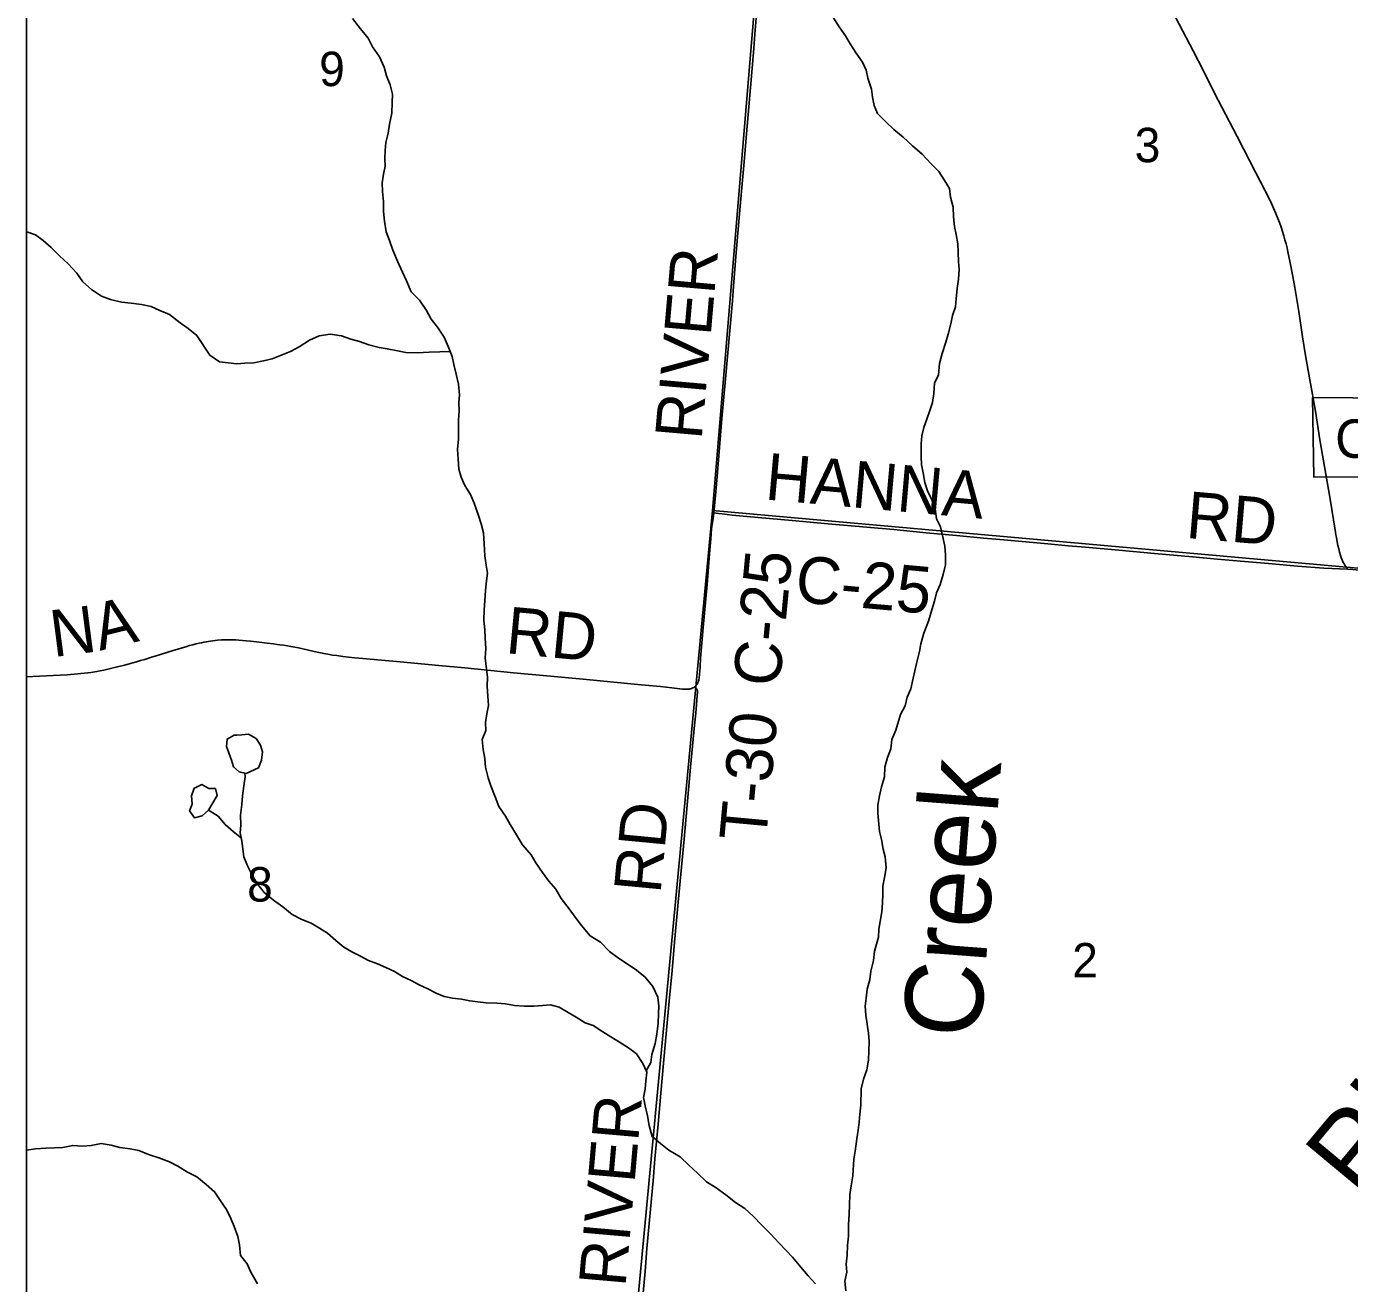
# Model space of a CAD drawing. Extents: x 0 to 1067, y 0 to 440.
# Drawn here: x 131 to 227.4, y 260 to 351.6 of the extents above; entities that cross this region are included whole.
import ezdxf

# ---------------------------------------------------------------- set-up
doc = ezdxf.new("R2010")
doc.units = 0
for name, color, linetype in [('GM_X_County_Road', 7, 'Continuous'), ('GM_X_County_Road_Text', 7, 'Continuous'), ('GM_X_Major_River_Text', 7, 'Continuous'), ('GM_X_Minor_Lake', 7, 'Continuous'), ('GM_X_Minor_River', 7, 'Continuous'), ('GM_X_Minor_River_Text', 7, 'Continuous'), ('GM_X_Section', 7, 'Continuous'), ('GM_X_Section_Text', 7, 'Continuous'), ('GM_X_State_Route', 7, 'Continuous'), ('GM_X_Township_Road', 7, 'Continuous'), ('GM_X_Township_Road_Text', 7, 'Continuous'), ('SH_Text', 7, 'Continuous')]:
    doc.layers.add(name, color=color, linetype=linetype)

msp = doc.modelspace()

# ---------------------------------------------------------------- linework, layer by layer
at = {"layer": 'GM_X_County_Road'}
for points in [[(179.683, 303.484), (179.722, 303.512), (179.774, 303.562), (179.809, 303.603), (179.837, 303.641), (179.898, 303.731), (179.93, 303.798), (179.955, 303.85), (179.971, 303.902), (179.986, 303.959), (179.996, 304.008), (180.014, 304.109), (180.03, 304.215), (180.043, 304.316), (180.053, 304.447), (180.064, 304.597), (180.084, 304.933), (180.123, 305.569), (180.172, 306.137), (180.315, 307.813), (180.606, 310.945), (180.769, 313.184), (180.865, 314.264), (180.929, 315.009), (180.95, 315.162), (180.97, 315.322), (180.993, 315.478), (181.034, 315.764), (181.059, 315.944), (181.089, 316.159)], [(181.089, 316.159), (181.248, 316.14), (181.433, 316.117), (181.694, 316.085), (182.429, 316.001), (183.494, 315.897), (186.789, 315.601), (188.619, 315.434), (189.96, 315.315), (191.671, 315.162), (192.495, 315.088), (194.197, 314.94), (196.554, 314.717), (198.781, 314.507), (200.746, 314.329), (202.216, 314.195), (203.565, 314.071), (205.421, 313.906), (206.902, 313.771), (208.168, 313.651), (210.606, 313.436), (213.2, 313.204), (215.977, 312.948), (217.792, 312.785), (219.453, 312.638), (221.511, 312.464), (223.627, 312.287), (225.535, 312.144), (227.25, 312.068)], [(131, 304.202), (131.941, 304.255), (133.46, 304.329), (133.963, 304.359), (134.22, 304.378), (134.491, 304.397), (134.732, 304.417), (134.964, 304.442), (135.235, 304.471), (135.462, 304.501), (135.689, 304.536), (136.123, 304.61), (136.38, 304.659), (136.635, 304.707), (136.937, 304.773), (137.218, 304.837), (137.514, 304.906), (137.845, 304.99), (138.155, 305.069), (138.413, 305.133), (138.747, 305.226), (139.028, 305.305), (139.319, 305.389), (139.633, 305.482), (140.044, 305.611), (140.459, 305.734), (140.849, 305.853), (141.702, 306.129), (142.032, 306.227), (142.348, 306.321), (142.614, 306.4), (142.885, 306.484), (143.127, 306.548), (143.378, 306.612), (143.595, 306.662), (143.754, 306.696), (143.931, 306.731), (144.118, 306.77), (144.261, 306.795), (144.414, 306.82), (144.587, 306.844), (144.74, 306.864), (144.932, 306.884), (145.223, 306.903), (145.43, 306.913), (145.628, 306.918), (145.845, 306.918), (146.032, 306.913), (146.264, 306.899), (146.476, 306.884), (146.747, 306.864), (147.009, 306.844), (147.319, 306.815), (147.753, 306.77), (148.163, 306.721), (148.533, 306.676), (148.996, 306.617), (149.262, 306.578), (149.474, 306.548), (149.736, 306.509), (150.017, 306.464), (150.273, 306.42), (150.56, 306.366), (150.816, 306.312), (152.173, 306.016), (152.424, 305.961), (152.666, 305.912), (152.968, 305.857), (153.307, 305.798), (153.618, 305.754), (154.042, 305.695), (154.456, 305.645), (154.934, 305.596), (155.521, 305.537), (158.23, 305.294), (161.06, 305.029), (162.937, 304.862), (166.495, 304.511), (168.922, 304.284), (171.566, 304.038), (175.802, 303.629), (177.208, 303.498), (178.022, 303.414), (178.801, 303.322), (178.979, 303.308), (179.098, 303.305), (179.195, 303.305), (179.278, 303.315), (179.342, 303.325), (179.412, 303.344), (179.472, 303.364), (179.52, 303.384), (179.569, 303.409), (179.623, 303.443), (179.683, 303.484)]]:
    msp.add_lwpolyline(points, dxfattribs=at)
at = {"layer": 'GM_X_Minor_Lake'}
for points in [[(146.341, 299.969), (146.123, 299.955), (145.619, 299.667), (145.565, 299.123), (145.74, 298.665), (145.936, 298.139), (146.087, 297.66), (146.49, 297.29), (147.01, 297.168)], [(147.01, 297.168), (147.901, 297.585), (148.136, 298.127), (148.191, 298.74), (148.063, 299.22), (147.73, 299.725), (147.19, 300.029), (146.691, 299.991), (146.341, 299.969)], [(143.348, 296.149), (143.227, 296.091), (143.014, 295.526), (143.073, 294.934), (142.884, 294.437), (143.239, 293.931), (143.808, 294.081), (144.268, 294.483)], [(144.268, 294.483), (144.898, 295.564), (144.769, 296.066), (144.293, 296.074), (143.775, 296.355), (143.348, 296.149)]]:
    msp.add_lwpolyline(points, dxfattribs=at)
at = {"layer": 'GM_X_Minor_River'}
for points in [[(157.147, 342.574), (157.188, 343.166), (157.367, 343.844), (157.454, 344.503), (157.614, 345.296), (157.637, 346.07), (157.678, 346.685), (157.493, 347.374), (157.239, 348.02), (157.076, 348.664), (156.733, 349.404), (156.208, 350.127), (155.908, 350.774), (155.336, 351.452), (154.766, 352.199)], [(198.255, 339.82), (197.864, 340.448), (197.472, 341.052), (196.897, 341.64), (196.257, 342.32), (195.568, 342.911), (194.881, 343.548), (194.215, 344.115), (193.617, 344.68), (193.019, 345.268), (192.763, 345.869), (192.644, 346.465), (192.571, 347.06), (192.321, 347.866), (192.179, 348.44), (191.922, 349.018), (191.464, 349.67), (191.029, 350.367), (190.681, 350.947), (190.222, 351.599), (189.765, 352.32)], [(176.153, 275.489), (176.49, 276.09), (176.576, 276.681), (176.804, 277.474), (176.938, 278.155), (177.029, 278.951), (177.049, 279.636), (177.089, 280.205), (177.016, 280.847), (176.652, 281.635), (176.08, 282.314), (175.457, 282.813), (174.765, 283.291), (174.14, 283.698), (173.493, 284.175), (172.83, 284.857), (172.07, 285.337), (171.455, 286.087), (170.972, 286.696), (170.534, 287.303), (169.964, 288.051), (169.574, 288.725), (169.067, 289.311), (168.607, 289.942), (168.127, 290.642), (167.78, 291.223), (167.141, 291.973), (166.707, 292.695), (166.251, 293.439), (165.904, 294.043), (165.424, 294.766), (165.148, 295.459), (164.831, 296.268), (164.643, 296.845), (164.438, 297.627), (164.41, 298.245), (164.27, 298.911), (164.201, 299.643), (164.47, 300.297), (164.442, 300.869), (164.551, 301.505), (164.66, 302.118), (164.612, 302.804), (164.565, 303.536), (164.607, 304.197), (164.51, 304.77), (164.42, 305.595), (164.463, 306.278), (164.417, 307.033), (164.411, 307.627), (164.318, 308.337), (164.34, 309.09), (164.405, 309.75), (164.45, 310.502), (164.516, 311.207), (164.601, 311.775), (164.504, 312.349), (164.41, 313.036), (164.345, 313.906), (164.3, 314.706), (164.137, 315.372), (163.95, 315.972), (163.612, 316.872), (163.357, 317.496), (162.944, 318.17), (162.688, 318.772), (162.5, 319.348), (162.454, 320.102), (162.406, 320.788), (162.474, 321.562), (162.492, 322.155), (162.492, 322.931), (162.534, 323.614), (162.506, 324.208), (162.546, 324.777), (162.477, 325.555), (162.316, 326.267), (162.132, 326.98), (162.012, 327.554), (161.738, 328.292), (161.439, 328.963), (160.96, 329.708), (160.499, 330.292), (160.153, 330.919), (159.651, 331.664), (159.031, 332.276), (158.691, 333.085), (158.413, 333.71), (158.027, 334.52), (157.708, 335.305), (157.456, 336.02), (157.201, 336.643), (157.087, 337.422), (157.017, 338.131), (157.016, 338.861), (156.946, 339.593), (156.919, 340.232), (157.028, 340.845), (157.137, 341.434), (157.108, 342.005), (157.147, 342.574)], [(191.397, 269.628), (191.514, 270.538), (191.6, 271.152), (191.686, 271.743), (191.726, 272.335), (191.79, 272.973), (191.826, 274.182), (192.005, 274.885), (192.23, 275.563), (192.365, 276.267), (192.405, 277.636), (192.354, 278.232), (192.259, 278.897), (192.164, 279.539), (192.115, 280.203), (192.178, 280.772), (192.265, 281.432), (192.445, 282.134), (192.531, 282.748), (192.713, 283.519), (192.801, 284.202), (193.082, 285.221), (193.122, 285.813), (193.207, 286.382), (193.318, 287.086), (193.383, 287.724), (193.402, 288.385), (193.396, 288.956), (193.528, 289.592), (193.639, 290.273), (193.572, 291.075), (193.429, 291.65), (193.313, 292.361), (193.171, 292.936), (193.027, 294.265), (193.045, 294.858), (193.156, 295.54), (193.312, 296.197), (193.515, 296.922), (193.536, 297.629), (193.738, 298.331), (193.984, 298.962), (194.05, 299.645), (194.343, 300.321), (194.695, 301.475), (195.033, 302.104), (195.164, 302.717), (195.433, 303.325), (195.615, 304.118), (195.851, 305.184), (196.081, 306.045), (196.166, 306.613), (196.394, 307.405), (196.738, 308.262), (196.968, 309.1), (197.168, 309.733), (197.322, 310.322), (197.591, 310.953), (197.794, 311.677), (197.974, 312.379), (197.973, 313.11), (197.923, 313.727), (197.741, 314.509), (197.6, 315.152), (197.321, 315.731), (197.206, 316.465), (196.953, 317.157), (196.652, 317.76), (196.465, 318.382), (196.349, 319.07), (196.23, 319.667), (196.202, 320.261), (196.184, 321.197), (196.246, 321.789), (196.378, 322.378), (196.6, 322.988), (196.824, 323.62), (197.023, 324.207), (197.111, 324.866), (197.178, 325.617), (197.447, 326.225), (197.539, 327.044), (197.72, 327.791), (197.994, 328.604), (198.171, 329.192), (198.352, 329.94), (198.484, 330.552), (198.685, 331.185), (198.748, 331.776), (198.815, 332.527), (198.926, 333.208), (198.97, 333.914), (198.918, 334.486), (198.892, 335.148), (198.865, 335.787), (198.748, 336.452), (198.629, 337.049), (198.558, 337.735), (198.533, 338.443), (198.327, 339.179), (198.255, 339.82)], [(161.872, 327.931), (161.112, 327.901), (160.337, 327.879), (159.47, 327.837), (158.651, 327.862), (158.04, 327.972), (157.293, 328.132), (156.704, 328.219), (155.958, 328.424), (155.259, 328.651), (154.627, 328.83), (153.951, 329.079), (153.135, 329.195), (152.334, 329.06), (151.619, 328.763), (150.876, 328.261), (150.229, 327.938), (148.892, 327.386), (148.273, 327.246), (147.563, 327.108), (146.902, 327.082), (146.332, 327.031), (145.696, 327.097), (145.061, 327.185), (144.369, 327.662), (143.409, 329.106), (142.787, 329.604), (142.206, 330.01), (141.428, 330.627), (140.708, 330.923), (140.079, 331.216), (139.377, 331.352), (138.628, 331.443), (137.925, 331.533), (137.133, 331.717), (136.48, 331.965), (135.743, 332.444), (135.099, 333.011), (134.662, 333.641), (134.044, 334.321), (133.402, 334.911), (132.804, 335.5), (132.227, 336.019), (131.647, 336.425), (131.016, 336.649), (131, 336.652)], [(188.496, 259.963), (187.967, 260.55), (187.415, 261.161), (186.822, 261.91), (185.85, 262.922), (185.21, 263.604), (184.591, 264.24), (183.95, 264.899), (183.351, 265.442), (182.659, 265.898), (181.969, 266.444), (181.255, 266.968), (180.562, 267.401), (179.897, 268.015), (179.277, 268.605), (178.635, 269.218), (177.806, 269.701), (177.206, 270.199), (176.583, 270.697), (176.379, 271.503), (176.263, 272.215), (176.079, 272.928), (175.961, 273.548), (176.092, 274.138), (176.132, 274.754), (176.197, 275.391), (175.919, 276.016), (175.461, 276.716), (174.86, 277.168), (174.211, 277.576), (173.585, 277.961), (173.004, 278.321), (172.289, 278.8), (171.702, 278.978), (171.054, 279.408), (170.472, 279.746), (169.823, 280.131), (169.19, 280.288), (168.598, 280.26), (167.981, 280.188), (167.276, 280.21), (166.571, 280.254), (165.914, 280.366), (165.278, 280.408), (164.504, 280.432), (163.892, 280.519), (163.302, 280.583), (162.691, 280.716), (162.033, 280.781), (161.445, 280.914), (160.86, 281.16), (160.254, 281.475), (159.625, 281.746), (159.042, 282.061), (158.413, 282.354), (157.809, 282.738), (157.18, 283.008), (156.573, 283.278), (155.92, 283.527), (155.337, 283.841), (154.709, 284.157), (154.127, 284.495), (153.549, 284.992), (152.927, 285.514), (152.346, 285.897), (151.742, 286.258), (151.066, 286.507), (150.372, 286.894), (149.682, 287.44), (148.99, 287.918), (148.323, 288.486), (147.797, 289.165), (147.428, 289.792), (147.105, 290.442), (146.851, 291.089), (146.703, 292.235), (146.561, 292.833), (146.623, 293.402), (146.599, 294.133), (146.69, 294.907), (146.754, 295.544), (146.843, 296.272), (146.93, 296.909), (146.908, 297.205)], [(146.667, 292.443), (146.064, 292.933), (145.485, 293.446), (144.975, 294.047), (144.393, 294.423), (144.268, 294.483)], [(147.832, 259.954), (147.356, 260.814), (147.077, 261.416), (146.594, 262.025), (146.526, 262.803), (146.407, 263.401), (146.132, 264.14), (145.899, 264.718), (145.576, 265.368), (145.096, 266.09), (144.703, 266.673), (144.104, 267.194), (143.415, 267.763), (142.742, 268.104), (142.026, 268.537), (141.42, 268.852), (140.655, 269.15), (139.887, 269.378), (139.19, 269.674), (138.556, 269.807), (137.808, 269.899), (137.175, 270.055), (136.45, 270.191), (135.717, 270.031), (135.101, 270.004), (134.374, 270.049), (133.64, 269.889), (133.048, 269.884), (132.41, 269.858), (131.657, 269.789), (131, 269.703)], [(190.712, 259.438), (190.641, 260.149), (190.774, 260.807), (190.723, 261.38), (190.81, 262.039), (190.832, 262.77), (190.897, 263.43), (190.898, 264.252), (190.944, 265.05), (190.985, 265.689), (191.008, 266.465), (191.095, 267.101), (191.207, 267.829), (191.288, 269.037), (191.397, 269.628)]]:
    msp.add_lwpolyline(points, dxfattribs=at)
at = {"layer": 'GM_X_Section'}
for points in [[(185.99, 376.405), (246.65, 370.913), (240.782, 310.986), (180.984, 316.33)], [(180.984, 316.33), (240.782, 310.986), (235.406, 252.097), (175.453, 257.739)]]:
    msp.add_lwpolyline(points, close=True, dxfattribs=at)
at = {"layer": 'GM_X_State_Route'}
for points in [[(214.756, 352.26), (216.008, 349.845), (216.76, 348.386), (217.557, 346.817), (219.225, 343.597), (220.576, 340.948), (221.548, 339.079), (221.72, 338.714), (221.873, 338.383), (222.036, 337.999), (222.189, 337.629), (222.307, 337.328), (222.425, 336.998), (222.529, 336.677), (222.622, 336.357), (222.706, 336.06), (222.781, 335.78), (222.854, 335.483), (222.921, 335.198), (223.086, 334.393), (223.279, 333.387), (223.422, 332.598), (223.708, 330.847), (223.984, 328.998), (224.191, 327.646), (224.522, 325.863), (224.921, 323.567), (225.257, 321.476), (225.609, 319.393), (225.967, 317.298), (226.393, 314.762), (226.42, 314.561), (226.454, 314.358), (226.514, 314.043), (226.564, 313.789), (226.618, 313.54), (226.677, 313.308), (226.751, 313.052), (226.802, 312.902), (226.843, 312.791), (226.898, 312.662), (226.95, 312.555), (227.007, 312.449), (227.074, 312.354), (227.14, 312.246), (227.201, 312.148), (227.25, 312.068)], [(227.25, 312.068), (227.659, 312.025), (228.597, 311.945), (232.88, 311.581), (238.674, 311.072), (241.117, 310.852)]]:
    msp.add_lwpolyline(points, dxfattribs=at)
at = {"layer": 'GM_X_Township_Road'}
for points in [[(252.4, 425.107), (131, 425.107), (131, 200.68)], [(184.245, 353.115), (184.082, 351.072), (183.992, 350.032), (183.927, 349.14), (183.465, 343.793), (183.3, 341.749), (183.181, 340.413), (183.016, 338.519), (182.722, 335.14), (182.531, 332.687), (182.438, 331.61), (181.915, 325.669), (181.681, 323.033), (181.346, 319.097), (181.203, 317.425), (181.089, 316.159)], [(181.089, 316.159), (181.059, 315.944), (181.034, 315.764), (180.993, 315.478), (180.97, 315.322), (180.95, 315.162), (180.929, 315.009), (180.865, 314.264), (180.769, 313.184), (180.606, 310.945), (180.315, 307.813), (180.172, 306.137), (180.123, 305.569), (180.084, 304.933), (180.064, 304.597), (180.053, 304.447), (180.043, 304.316), (180.03, 304.215), (180.014, 304.109), (179.996, 304.008), (179.986, 303.959), (179.971, 303.902), (179.955, 303.85), (179.93, 303.798), (179.898, 303.731), (179.837, 303.641), (179.809, 303.603), (179.774, 303.562), (179.722, 303.512), (179.683, 303.484)], [(179.683, 303.484), (179.768, 303.391), (179.825, 303.33), (179.869, 303.27), (179.896, 303.209), (179.899, 303.14), (179.768, 301.571), (179.685, 300.681), (179.397, 297.623), (179.119, 294.594), (178.914, 292.366), (178.499, 287.793), (178.223, 284.859), (178.045, 282.802), (177.839, 280.566), (177.645, 278.457), (177.425, 276.045), (177.233, 273.86), (177.038, 271.596), (176.8, 269.078), (176.664, 267.463), (176.477, 265.411), (176.211, 262.531), (176.075, 260.863), (175.816, 258.008)]]:
    msp.add_lwpolyline(points, dxfattribs=at)
at = {"layer": 'SH_Text'}
for points in [[(131, 425.107), (539, 425.107), (539, 17.107), (131, 17.107)], [(270.306, 304.543), (254.006, 324.33), (224.715, 324.575), (224.812, 318.764), (253.556, 318.883)]]:
    msp.add_lwpolyline(points, close=True, dxfattribs=at)

# ---------------------------------------------------------------- texts
at = {"layer": 'GM_X_County_Road_Text'}
for s, height, rotation, p in [('HANNA', 3.4091, 354.90758, (184.753, 317.146)), ('RD', 3.4091, 355.15695, (215.425, 314.343)), ('C-25', 3.4091, 84.56213, (185.876, 303.419)), ('C-25', 3.4091, 354.87048, (186.944, 309.678)), ('A', 3.409, 13.7321, (136.337, 306.101)), ('N', 3.409, 7.37985, (132.956, 305.64)), ('RD', 3.4091, 354.58225, (165.855, 305.945))]:
    msp.add_text(s, height=height, rotation=rotation, dxfattribs=at).set_placement(p)
at = {"layer": 'GM_X_Major_River_Text'}
msp.add_text('River', height=5.6799, rotation=50.21475, dxfattribs=at).set_placement((228.199, 266.028))
at = {"layer": 'GM_X_Minor_River_Text'}
msp.add_text('Creek', height=5.677, rotation=85.61539, dxfattribs=at).set_placement((200.491, 277.764))
at = {"layer": 'GM_X_Section_Text'}
for s, p in [('9', (152.329, 347.276)), ('3', (211.754, 341.726)), ('8', (147.079, 287.826)), ('2', (207.204, 282.295))]:
    msp.add_text(s, height=2.511, rotation=0.00001, dxfattribs=at).set_placement(p)
at = {"layer": 'GM_X_Township_Road_Text'}
for s, rotation, p in [('RIVER', 85.00959, (180.194, 321.439)), ('T-30', 84.70542, (184.877, 292.154)), ('RD', 84.58394, (177.195, 288.349)), ('RIVER', 84.98966, (174.643, 259.682))]:
    msp.add_text(s, height=3.4091, rotation=rotation, dxfattribs=at).set_placement(p)
at = {"layer": 'SH_Text'}
msp.add_text('CHP-296-0021', height=2.8, dxfattribs=at).set_placement((226.36, 320.177))

doc.saveas('drawing.dxf')
